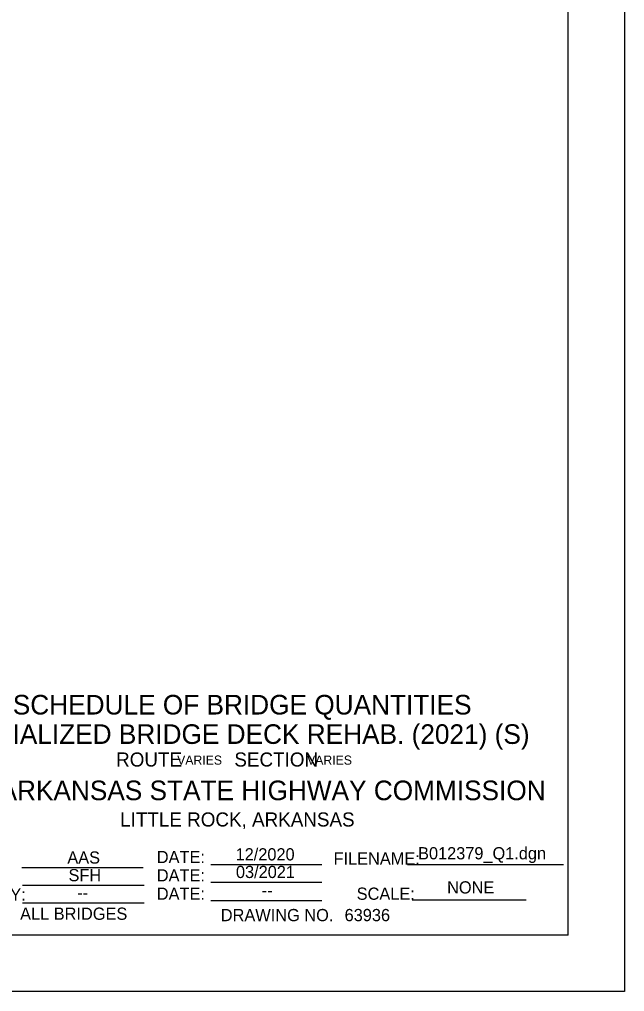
# Model space of a CAD drawing. Extents: x 16 to 1228740, y 11 to 152440.
# Drawn here: x 17.975 to 18.49, y 10.709 to 11.538 of the extents above; entities that cross this region are included whole.
import ezdxf

# ---------------------------------------------------------------- set-up
doc = ezdxf.new("R2010")
doc.units = 0
for name, color, linetype in [('B_Copy In', 7, 'Continuous'), ('B_Text', 7, 'Continuous'), ('B_Title Text', 7, 'Continuous'), ('R_Border', 7, 'Continuous')]:
    doc.layers.add(name, color=color, linetype=linetype)

msp = doc.modelspace()

# ---------------------------------------------------------------- linework, layer by layer
at = {"layer": 'B_Text'}
for p, q in [((17.97661, 10.81515), (18.08021, 10.81515)), ((18.13771, 10.81765), (18.23221, 10.81765)), ((18.30529, 10.81765), (18.43835, 10.81765)), ((17.97721, 10.80015), (18.08081, 10.80015)), ((18.13771, 10.80265), (18.23221, 10.80265)), ((18.13771, 10.80265), (18.23221, 10.80265)), ((17.97721, 10.78515), (18.08081, 10.78515)), ((18.13771, 10.78703), (18.23221, 10.78703)), ((18.30917, 10.78765), (18.40631, 10.78765))]:
    msp.add_line(p, q, dxfattribs=at)
at = {"layer": 'R_Border'}
for q in [(18.44221, 12.49475), (15.78327, 10.75755)]:
    msp.add_line((18.44221, 10.75755), q, dxfattribs=at)
msp.add_lwpolyline([(15.65694, 12.54282), (18.49027, 12.54282), (18.49027, 10.70949), (15.65694, 10.70949)], close=True, dxfattribs=at)

# ---------------------------------------------------------------- texts
at = {"layer": 'B_Copy In'}
for s, height, p in [('SCHEDULE OF BRIDGE QUANTITIES', 0.0167, (17.96903, 10.94549)), ('SPECIALIZED BRIDGE DECK REHAB. (2021) (S)', 0.0167, (17.908, 10.92044)), ('12/2020', 0.0104, (18.15886, 10.82119)), ('B012379_Q1.dgn', 0.0104, (18.31434, 10.8221)), ('AAS', 0.0104, (18.0155, 10.81846)), ('03/2021', 0.0104, (18.15915, 10.80619)), ('SFH', 0.0104, (18.01647, 10.80346)), ('NONE', 0.0104, (18.3391, 10.79302)), ('--', 0.0104, (18.02387, 10.78846)), ('--', 0.0104, (18.18115, 10.79057)), ('ALL BRIDGES', 0.0104166, (17.97523, 10.7706)), ('63936', 0.010417, (18.25173, 10.76944))]:
    msp.add_text(s, height=height, dxfattribs=at).set_placement(p)
at = {"layer": 'B_Text'}
for s, height, p in [('DATE:', 0.010417, (18.09171, 10.8189)), ('FILENAME:', 0.010417, (18.24229, 10.81765)), ('DATE:', 0.010417, (18.09171, 10.80328)), ('DATE:', 0.010417, (18.09171, 10.78765)), ('SCALE:', 0.010417, (18.26201, 10.78765)), ('DESIGNED BY:', 0.0104166, (17.88091, 10.78695)), ('DRAWING NO.', 0.0104166, (18.14623, 10.76942))]:
    msp.add_text(s, height=height, dxfattribs=at).set_placement(p)
at = {"layer": 'B_Title Text'}
for s, height, p in [('ROUTE          SECTION ', 0.012, (18.05705, 10.90115)), ('ROUTE          SECTION ', 0.012, (18.05705, 10.90115)), ('                VARIES                         VARIES', 0.0078, (18.06267, 10.90274)), ('ARKANSAS STATE HIGHWAY COMMISSION', 0.0167, (17.95772, 10.8725)), ('LITTLE ROCK, ARKANSAS', 0.012, (18.0605, 10.85007))]:
    msp.add_text(s, height=height, dxfattribs=at).set_placement(p)

doc.saveas('drawing.dxf')
